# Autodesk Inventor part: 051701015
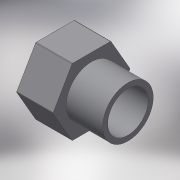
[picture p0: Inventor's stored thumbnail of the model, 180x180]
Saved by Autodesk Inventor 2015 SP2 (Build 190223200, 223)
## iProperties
Created: 2017-10
Part Number: 051701015
Material: Generic
Description: PLASSON THREADED PLUG PVC 1.1/2"
Document SubType Name: Modeling
Designer: KIM
Density: 1 g/cm^3
Appearance: Default
Author: KIM
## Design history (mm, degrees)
derived "051701.ipt"
feature "Solid1::051701.ipt"
tag "TaggingFeature1"
body "Solid1"
other parameters: "d0" = 44, "d1" = 47.803, "d2" = 1, "d3" = 16, "d4" = 51, "d6" = 38.2424, "d9" = 16, "d10" = 0, "d18" = 0.51, "d19" = 22, "d20" = 30.8, "R_" = 47.803, "C_" = 51, "B_" = 16, "Lt_" = 22, "H_" = 44
